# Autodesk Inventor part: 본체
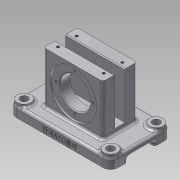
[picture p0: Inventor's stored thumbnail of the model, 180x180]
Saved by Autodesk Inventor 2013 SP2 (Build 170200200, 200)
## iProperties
Created: 2025-04
Part Number: 본체
Material: 알루미늄 6061
Document SubType Name: Modeling
Designer: i
Density: 2.71 g/cm^3
Mass: 546.851 g
Surface Area: 435.403 cm^2
Volume: 201.79 cm^3
Author: i
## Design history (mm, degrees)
sketch "스케치1"
  geometry: L1 (-35, -36)-(35, -36); L2 (35, -36)-(35, 36); L3 (35, 36)-(-35, 36); L4 (-35, 36)-(-35, -36); L5 (-35, -36)-(35, 36); L6 (35, -36)-(-35, 36); 1 further point
  constraints: 12 end point, 2 midpoint, 2 parallel, 1 horizontal, 1 perpendicular
  dimensions: "d0" = 70 distance of L2.end L3.end; "d2" = 72 distance of L3.end L1.start
extrude "돌출1" new body sketch "스케치1" stored distance "d3" = 40; taper "d4" = 0 deg
sketch "스케치2"
  geometry: L1 (70, -40)-(70, 0) reference; L2 (0, 0)-(70, 0) reference; L3 (0, 0)-(0, -40) reference; L4 (70, -40)-(0, -40) reference; L5 (-25, -56)-(95, -56); L6 (95, -56)-(95, 16); L7 (95, 16)-(-25, 16); L8 (-25, 16)-(-25, -56); L9 (-25, -56)-(95, 16); L10 (95, -56)-(-25, 16); 1 further point
  constraints: 12 end point, 2 midpoint, 2 parallel, 1 horizontal, 1 perpendicular
  dimensions: "d5" = 120 distance of L6.end L7.end; "d7" = 72 distance of L5.end L6.end
extrude "돌출2" join sketch "스케치2" distance "d8" = 12; taper "d9" = 0 deg
sketch "스케치3"
  geometry: L1 (40, 0)-(0, 0) reference; L2 (14, 0)-(26, 0); L3 (26, 0)-(26, -55); L4 (26, -55)-(14, -55); L5 (14, -55)-(14, 0); 2 further points
  constraints: 8 end point, 2 parallel, 1 horizontal, 1 midpoint, 1 perpendicular, 1 point on line, 1 vertical alignment
  dimensions: "d10" = 12 distance between parallel lines of L3 L5; "d12" = 55 distance of L2.end L3.end
extrude "돌출3" cut sketch "스케치3" distance "d13" = 79; taper "d14" = 0 deg
sketch "스케치4"
  geometry: L1 (35, -24)-(35, 36) reference; L2 (35, 36)-(-35, 36) reference; C1 r 17 at (0, 6); 3 further points
  constraints: 2 midpoint, 1 centre point, 1 horizontal alignment, 1 vertical alignment
  dimensions: "d15" = 34 diameter of C1
extrude "돌출4" join sketch "스케치4" distance "d16" = 7; taper "d17" = 0 deg
sketch "스케치5"
  geometry: C1 r 17 at (0, 0) reference; C2 r 11 at (0, 0); 1 further point
  constraints: 1 centre point, 1 coincident
  dimensions: "d18" = 22 diameter of C2
extrude "돌출5" cut sketch "스케치5" distance "d19" = 86; taper "d20" = 0 deg
sketch "스케치6"
  geometry: C1 r 11 at (0, 6) reference; C2 r 18 at (0, 6); 1 further point
  constraints: 1 centre point, 1 coincident
  dimensions: "d21" = 36 diameter of C2
extrude "돌출6" cut sketch "스케치6" distance "d22" = 21.75; taper "d23" = 0 deg
sketch "스케치7"
  geometry: C1 r 18 at (0, 6) reference; C2 r 27.5 at (0, 6); 1 further point
  constraints: 1 centre point, 1 coincident
  dimensions: "d24" = 55 diameter of C2
extrude "돌출7" cut sketch "스케치7" distance "d25" = 2; taper "d26" = 0 deg
sketch "스케치8"
  geometry: C1 r 18 at (0, 0) reference; C2 r 27.5 at (0, 0) reference; C3 r 18 at (0, 0); 1 further point
  constraints: 1 centre point, 1 coincident
  dimensions: "d27" = 36 diameter of C3
sketch "스케치9"
  geometry: C1 r 11 at (35, 25) reference; C2 r 15 at (35, 25); 1 further point
  constraints: 1 centre point, 1 coincident
  dimensions: "d28" = 30 diameter of C2
extrude "돌출8" cut sketch "스케치9" distance "d29" = 5; taper "d30" = 0 deg
chamfer "모따기1" distance "d31" = 1; stored, may be unused: second distance "d32" = 2, angle "d33" = 45 deg
sketch "스케치10" dims "d34" = 44
  geometry: C1 r 19 at (0, 0) reference; 3 further points
  constraints: 2 vertical alignment, 1 coincident, 2 other
hole "구멍1" sketch "스케치10" at (0, 22) diameter "d35" = 3.242; stored, may be unused: countersink angle "d39" = 90 deg, drill point angle "d41" = 118 deg; dims "d36" = 8, "d37" = 4, "d38" = 2, "d40" = 10
fillet "모깎기1" dims "d45" = 9
sketch "스케치11"
  geometry: C1 r 8 at (-16, -7); C2 r 8 at (86, 47); C3 r 8 at (86, -7); C4 r 8 at (-16, 47); A1 r 9 centre (-16, -7) between (-25, -7) and (-16, -16) reference; A2 r 9 centre (86, -7) between (86, -16) and (95, -7) reference; A3 r 9 centre (86, 47) between (95, 47) and (86, 56) reference; A4 r 9 centre (-16, 47) between (-16, 56) and (-25, 47) reference; 1 further point
  constraints: 4 centre point, 4 coincident
  dimensions: "d46" = 16 diameter of C1; "d47" = 16 diameter of C2; "d48" = 16 diameter of C3; "d49" = 16 diameter of C4
extrude "돌출9" join sketch "스케치11" distance "d50" = 3; taper "d51" = 0 deg
sketch "스케치12"
  geometry: C1 r 8 at (0, 0) reference; C2 r 8 at (-102, 0) reference; C3 r 8 at (-102, -54) reference; C4 r 8 at (0, -54) reference; 1 further point
hole "구멍2" sketch "스케치12" at (0, 0), (-102, 0), (-102, -54), (0, -54) diameter "d52" = 9; stored, may be unused: countersink angle "d56" = 90 deg, drill point angle "d58" = 118 deg; dims "d53" = 2, "d54" = 4, "d55" = 2, "d57" = 20
node "작업 평면1"
sketch "스케치13"
  geometry: L1 (102, 0)-(0, 0) reference; 2 further points
  constraints: 1 vertical alignment, 1 other
  dimensions: "d60" = 5 distance from line of L1 point (51, 5)
feature "엠보싱1" sketch "스케치13" dims "d9" = 0, "d61" = 0.5, "d62" = 0
sketch "스케치14"
  geometry: 3 further points
  dimensions: "d63" = 54 distance of point (62, 9) point (8, 9); "d65" = 27 horizontal distance of point (35, 20) point (8, 9); "d66" = 27 horizontal distance of point (62, 9) point (35, 20); "d67" = 11 vertical distance of point (35, 20) point (62, 9)
hole "구멍3" sketch "스케치14" at (8, 9), (62, 9) diameter "d68" = 3.242; stored, may be unused: countersink angle "d72" = 90 deg, drill point angle "d74" = 118 deg; dims "d69" = 8, "d70" = 4, "d71" = 2, "d73" = 10
node "작업 평면2"
fillet "모깎기2" dims "d75" = 3
fillet "모깎기3" dims "d76" = 3
fillet "모깎기4" dims "d77" = 3
fillet "모깎기5" dims "d78" = 3
chamfer "모따기2" distance "d79" = 1; stored, may be unused: second distance "d80" = 2, angle "d81" = 45 deg
fillet "모깎기6" dims "d82" = 3
fillet "모깎기7" dims "d83" = 3
sketch "스케치15"
  geometry: L1 (54, 0)-(0, 0) reference; L2 (11, 5)-(43, 5); L3 (43, 5)-(43, 0); L4 (43, 0)-(11, 0); L5 (11, 0)-(11, 5); 2 further points
  constraints: 8 end point, 2 parallel, 1 horizontal, 1 midpoint, 1 perpendicular, 1 point on line, 1 vertical alignment
  dimensions: "d84" = 32 distance of L2.start L2.end; "d86" = 5 distance of L4.end L2.start
extrude "돌출10" cut sketch "스케치15" distance "d87" = 170; taper "d88" = 0 deg
fillet "모깎기8" dims "d89" = 3
fillet "모깎기9" dims "d90" = 3
chamfer "모따기3" distance "d91" = 1; stored, may be unused: second distance "d92" = 2, angle "d93" = 45 deg
node "솔리드1"
pattern_circular "원형 패턴1" dims angle "d43" = 360 deg
mirror "대칭1"
node "투영된 루프1"
node "투영된 루프2"
node "투영된 루프3"
